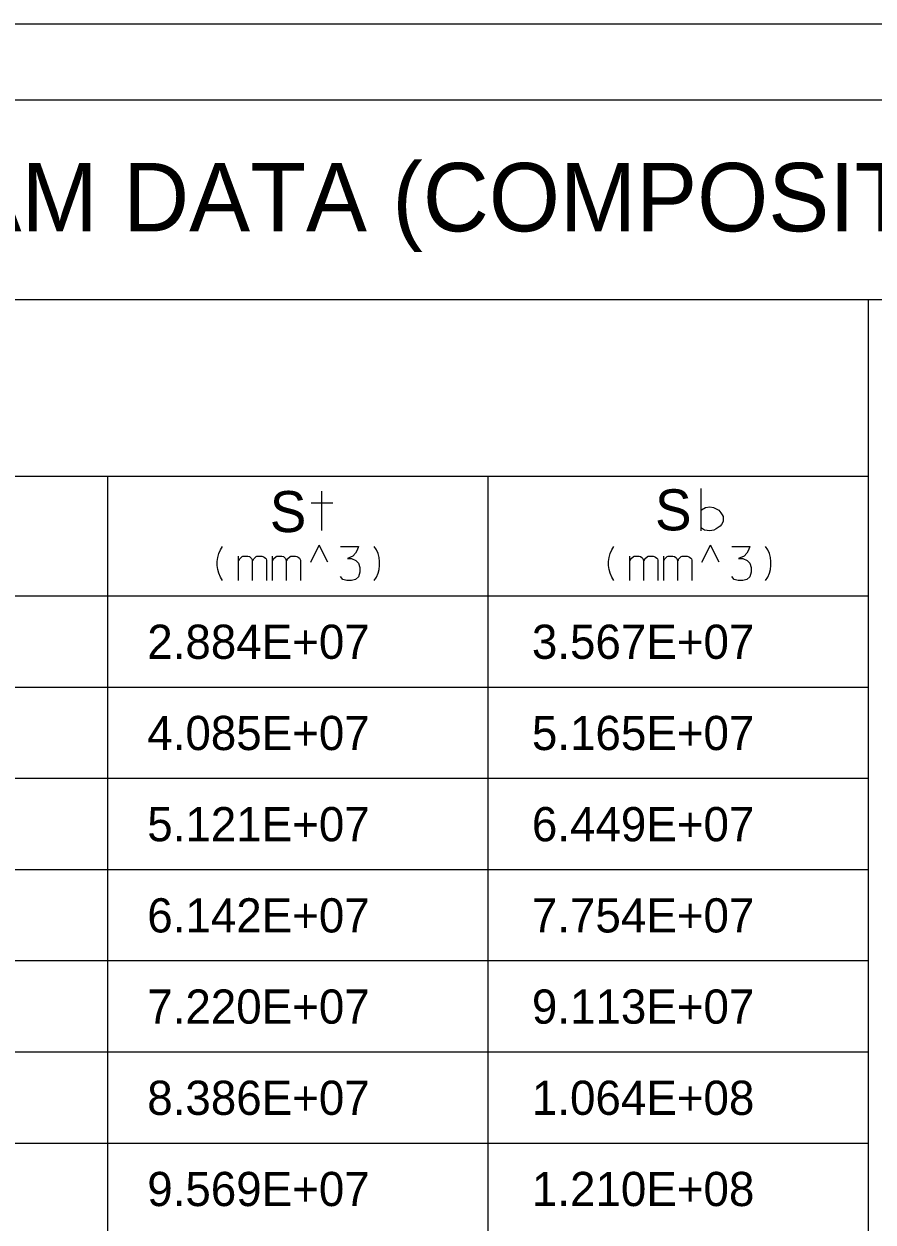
# Model space of a CAD drawing. Extents: x 635698 to 639877, y 296617 to 300175.
# Drawn here: x 636744.4 to 636818.9, y 299944.7 to 300049.8 of the extents above; entities that cross this region are included whole.
import ezdxf

# ---------------------------------------------------------------- set-up
doc = ezdxf.new("R2010")
doc.units = 0
doc.layers.add('2', color=7, linetype='Continuous')

msp = doc.modelspace()

# ---------------------------------------------------------------- linework, layer by layer
at = {"layer": '2'}
for p, q in [((636545.45, 300049.76), (637331.45, 300049.76)), ((637053.06, 300043.07), (636556.08, 300043.07)), ((637001.69, 300025.57), (636618.31, 300025.57)), ((636818.44, 300025.57), (636818.44, 299887.57)), ((636818.44, 300010.07), (636635.94, 300010.07)), ((636751.69, 300010.07), (636751.69, 299887.57)), ((636785.06, 300010.07), (636785.06, 299887.57)), ((636769.53, 300002.55), (636770.28, 300004.05)), ((636771.03, 300002.55), (636770.28, 300004.05)), ((636803.86, 300002.55), (636804.61, 300004.05)), ((636805.36, 300002.55), (636804.61, 300004.05)), ((636818.44, 299999.57), (636635.94, 299999.57)), ((636818.44, 299991.57), (636635.94, 299991.57)), ((636818.44, 299983.57), (636635.94, 299983.57)), ((636818.44, 299975.57), (636635.94, 299975.57)), ((636818.44, 299967.57), (636635.94, 299967.57)), ((636818.44, 299959.57), (636635.94, 299959.57)), ((636818.44, 299951.57), (636635.94, 299951.57))]:
    msp.add_line(p, q, dxfattribs=at)
for points in [[(636770.51, 300005.32), (636770.51, 300008.77)], [(636803.78, 300005.31), (636803.78, 300009.01)], [(636771.47, 300007.73), (636769.57, 300007.73)], [(636803.81, 300007.14), (636804.18, 300007.35), (636804.55, 300007.4), (636804.87, 300007.35), (636805.17, 300007.21), (636805.35, 300007.1), (636805.53, 300006.89), (636805.63, 300006.71), (636805.72, 300006.55), (636805.72, 300006.11), (636805.58, 300005.86), (636805.46, 300005.72), (636805.12, 300005.47), (636804.89, 300005.35), (636804.55, 300005.31), (636804.09, 300005.35), (636803.81, 300005.54)], [(636761.8, 300000.94), (636761.61, 300001.25), (636761.47, 300001.58), (636761.38, 300001.91), (636761.33, 300002.26), (636761.33, 300002.62), (636761.38, 300002.97), (636761.47, 300003.3), (636761.61, 300003.63), (636761.8, 300003.94)], [(636772.14, 300003.94), (636773.72, 300003.94), (636773.62, 300003.59), (636773.46, 300003.33), (636773.22, 300003.09), (636772.75, 300002.86), (636773.1, 300002.86), (636773.48, 300002.69), (636773.72, 300002.45), (636773.84, 300002.08), (636773.84, 300001.67), (636773.72, 300001.27), (636773.46, 300001.04), (636773.1, 300000.94), (636772.7, 300000.94), (636772.35, 300001.04), (636772.14, 300001.3)], [(636775.11, 300000.94), (636775.3, 300001.25), (636775.44, 300001.58), (636775.54, 300001.91), (636775.58, 300002.26), (636775.58, 300002.62), (636775.54, 300002.97), (636775.44, 300003.3), (636775.3, 300003.63), (636775.11, 300003.94)], [(636796.14, 300000.94), (636795.95, 300001.25), (636795.81, 300001.58), (636795.71, 300001.91), (636795.66, 300002.26), (636795.66, 300002.62), (636795.71, 300002.97), (636795.81, 300003.3), (636795.95, 300003.63), (636796.14, 300003.94)], [(636806.47, 300003.94), (636808.05, 300003.94), (636807.96, 300003.59), (636807.79, 300003.33), (636807.56, 300003.09), (636807.08, 300002.86), (636807.44, 300002.86), (636807.82, 300002.69), (636808.05, 300002.45), (636808.17, 300002.08), (636808.17, 300001.67), (636808.05, 300001.27), (636807.79, 300001.04), (636807.44, 300000.94), (636807.04, 300000.94), (636806.68, 300001.04), (636806.47, 300001.3)], [(636809.45, 300000.94), (636809.63, 300001.25), (636809.78, 300001.58), (636809.87, 300001.91), (636809.92, 300002.26), (636809.92, 300002.62), (636809.87, 300002.97), (636809.78, 300003.3), (636809.63, 300003.63), (636809.45, 300003.94)], [(636763.21, 300002.69), (636763.25, 300002.74), (636763.3, 300002.83), (636763.51, 300003.04), (636763.58, 300003.07), (636763.68, 300003.09), (636764.01, 300003.09), (636764.15, 300003.04), (636764.25, 300002.97), (636764.34, 300002.88), (636764.41, 300002.71), (636764.43, 300002.67), (636764.48, 300002.74), (636764.53, 300002.83), (636764.74, 300003.04), (636764.81, 300003.07), (636764.88, 300003.09), (636765.24, 300003.09), (636765.33, 300003.04), (636765.45, 300003), (636765.57, 300002.9), (636765.62, 300002.83), (636765.66, 300002.74), (636765.66, 300000.94)], [(636763.21, 300000.94), (636763.21, 300003.07)], [(636764.43, 300000.94), (636764.43, 300002.69)], [(636766.18, 300002.69), (636766.23, 300002.74), (636766.28, 300002.83), (636766.49, 300003.04), (636766.56, 300003.07), (636766.66, 300003.09), (636766.99, 300003.09), (636767.13, 300003.04), (636767.22, 300002.97), (636767.32, 300002.88), (636767.39, 300002.71), (636767.41, 300002.67), (636767.46, 300002.74), (636767.51, 300002.83), (636767.72, 300003.04), (636767.79, 300003.07), (636767.86, 300003.09), (636768.21, 300003.09), (636768.31, 300003.04), (636768.43, 300003), (636768.54, 300002.9), (636768.59, 300002.83), (636768.64, 300002.74), (636768.64, 300000.94)], [(636766.18, 300000.94), (636766.18, 300003.07)], [(636767.41, 300000.94), (636767.41, 300002.69)], [(636797.54, 300002.69), (636797.59, 300002.74), (636797.63, 300002.83), (636797.85, 300003.04), (636797.92, 300003.07), (636798.01, 300003.09), (636798.34, 300003.09), (636798.48, 300003.04), (636798.58, 300002.97), (636798.67, 300002.88), (636798.74, 300002.71), (636798.77, 300002.67), (636798.81, 300002.74), (636798.86, 300002.83), (636799.07, 300003.04), (636799.15, 300003.07), (636799.22, 300003.09), (636799.57, 300003.09), (636799.67, 300003.04), (636799.78, 300003), (636799.9, 300002.9), (636799.95, 300002.83), (636800, 300002.74), (636800, 300000.94)], [(636797.54, 300000.94), (636797.54, 300003.07)], [(636798.77, 300000.94), (636798.77, 300002.69)], [(636800.52, 300002.69), (636800.56, 300002.74), (636800.61, 300002.83), (636800.82, 300003.04), (636800.89, 300003.07), (636800.99, 300003.09), (636801.32, 300003.09), (636801.46, 300003.04), (636801.56, 300002.97), (636801.65, 300002.88), (636801.72, 300002.71), (636801.74, 300002.67), (636801.79, 300002.74), (636801.84, 300002.83), (636802.05, 300003.04), (636802.12, 300003.07), (636802.19, 300003.09), (636802.55, 300003.09), (636802.64, 300003.04), (636802.76, 300003), (636802.88, 300002.9), (636802.93, 300002.83), (636802.97, 300002.74), (636802.97, 300000.94)], [(636800.52, 300000.94), (636800.52, 300003.07)], [(636801.74, 300000.94), (636801.74, 300002.69)]]:
    msp.add_lwpolyline(points, dxfattribs=at)

# ---------------------------------------------------------------- texts
for s, height, p in [('ADJACENT BOX BEAM DATA (COMPOSITE CONSTRUCTION)', 6, (636664.35, 300031.57)), ('S', 3.6, (636765.94, 300005.19)), ('S', 3.6, (636799.74, 300005.34)), ('2.884E+07', 3, (636755.19, 299994.07)), ('3.567E+07', 3, (636788.94, 299994.07)), ('4.085E+07', 3, (636755.19, 299986.07)), ('5.165E+07', 3, (636788.94, 299986.07)), ('5.121E+07', 3, (636755.19, 299978.07)), ('6.449E+07', 3, (636788.94, 299978.07)), ('6.142E+07', 3, (636755.19, 299970.07)), ('7.754E+07', 3, (636788.94, 299970.07)), ('7.220E+07', 3, (636755.19, 299962.07)), ('9.113E+07', 3, (636788.94, 299962.07)), ('8.386E+07', 3, (636755.19, 299954.07)), ('1.064E+08', 3, (636788.94, 299954.07)), ('9.569E+07', 3, (636755.19, 299946.07)), ('1.210E+08', 3, (636788.94, 299946.07))]:
    msp.add_text(s, height=height, dxfattribs=at).set_placement(p)

doc.saveas('drawing.dxf')
